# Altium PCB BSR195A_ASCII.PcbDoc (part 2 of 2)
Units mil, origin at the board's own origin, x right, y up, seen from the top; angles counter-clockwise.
Board outline 4000 x 3000 mil, 4 copper layers (Top Layer, Signal Layer 1, Signal Layer 2, Bottom Layer), stack 64.4 mil thick; 59 components, 14 nets, 91 pads, 35 vias.
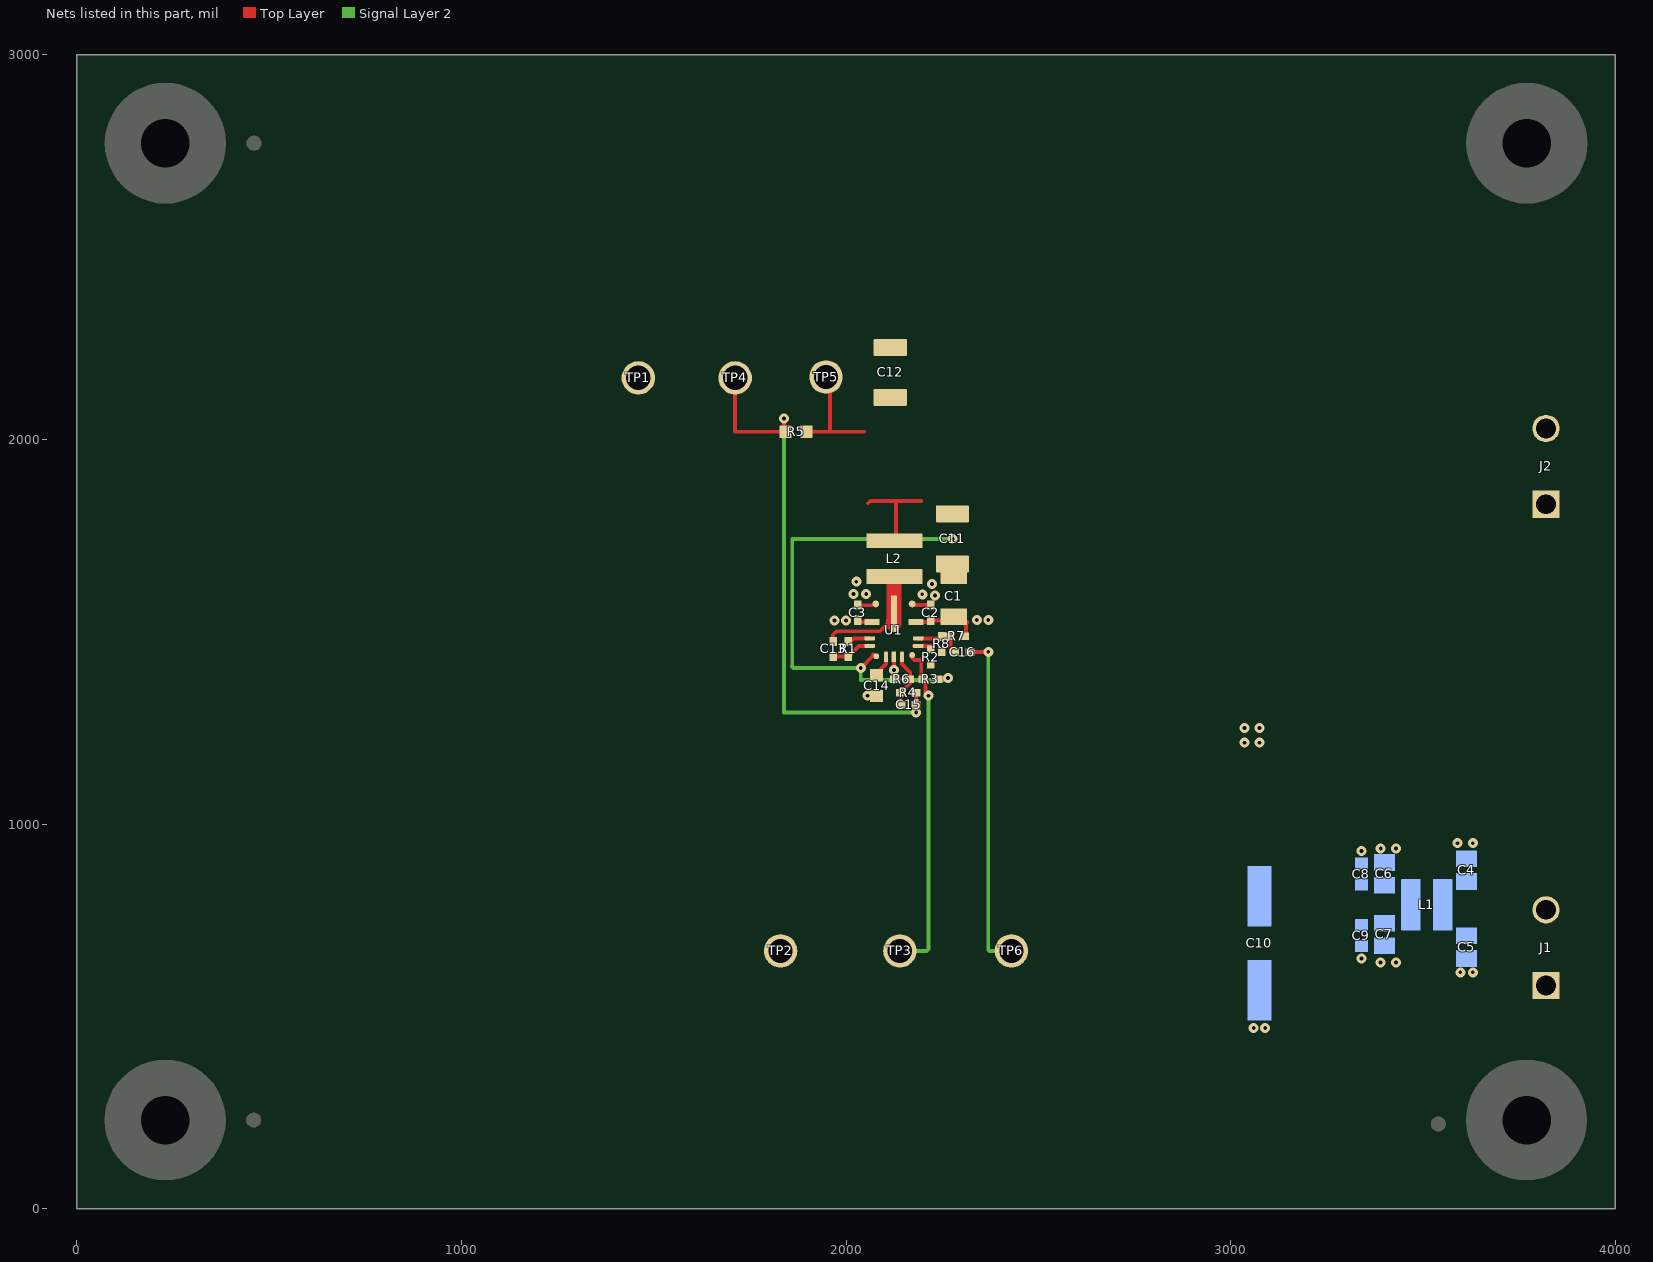
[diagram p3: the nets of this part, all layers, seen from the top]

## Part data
C1 C4 C5 C6 C7: library part CMP-0008814-2, "CAP, CERM, 2.2 uF, 50 V, +/- 10%, X7R, AEC-Q200 Grade 1, 1206"
C2 C3 C13: library part CMP-0006356-2, "CAP, CERM, 0.1 uF, 50 V, +/- 10%, X7R, AEC-Q200 Grade 1, 0402"
C8 C9: library part CMP-0008022-2, "CAP, CERM, 0.47 uF, 50 V, +/- 10%, X7R, AEC-Q200 Grade 1, 0805"
C10: library part CMP-0011168-2, "CAP, AL, 22 uF, 50 V, +/- 20%, 0.7 ohm, SMD"
C11 C12: library part CMP-0092443-1, "Multilayer Ceramic Capacitor 47uF 20% 10V 1210 T/R"
C14: library part CMP-0006831-4, "CAP, CERM, 1 uF, 16 V, +/- 10%, X7R, 0603"
C15: library part CMP-0006311-2, "CAP, CERM, 22 pF, 50 V, +/- 5%, C0G/NP0, AEC-Q200 Grade 1, 0402"
C16: library part CMP-0006314-2, "CAP, CERM, 1000 pF, 50 V, +/- 10%, X7R, AEC-Q200 Grade 1, 0402"
FID1 FID2 FID3 FID4 FID5 FID6: library part CMP-0077181-1, "Fiducial mark.  There is nothing to buy or mount."
H1 H2 H3 H4: library part CMP-0003617-1, "Machine Screw, Round, #4-40 x 1/4, Nylon, Philips panhead"
H5 H6 H7 H8: library part CMP-0003610-1
J1 J2: library part CMP-0054828-1, "Terminal Block, 5 mm, 2x1, Tin, TH"
L1: library part CMP-0087867-1, "1µH Shielded Molded Inductor 4A 32mOhm Max 2-SMD"
L2: library part CMP-0084012-1, "Inductor, Shielded, Metal Composite, 1.5 µH, 5.8 A, 0.019 ohm, SMD"
LBL1: library part CMP-0003625-1
Logo1: library part CMP-0074838-1, "Texas Instrument Corporate Signature"
Logo2: library part CMP-0074769-1
Logo3: library part CMP-0074847-1, "FCC_disclaimer"
LOGO4: library part CMP-0074837-1, "IEC 61010-1 Hot Surface Warning"
Logo5: library part CMP-0074844-1, "CE Mark"
R1: library part CMP-0081856-1, "RES, 0, 0%, 0.2 W, AEC-Q200 Grade 0, 0402"
R2: library part CMP-0091636-1, "5.9 kOhms ±1% 0.1W, 1/10W Chip Resistor 0402 (1005 Metric) Automotive AEC-Q200 Thick Film"
R3 R4 R8: library part CMP-0026768-2, "RES, 100 k, 0.5%, 0.063 W, AEC-Q200 Grade 0, 0402"
R5: library part CMP-0022736-4, "RES, 100, 1%, 0.1 W, 0603"
R6: library part CMP-0091635-1, "24.9 kOhms ±1% 0.1W, 1/10W Chip Resistor 0402 (1005 Metric) Automotive AEC-Q200 Thick Film"
R7: library part CMP-0026199-2, "RES, 255 k, 1%, 0.063 W, AEC-Q200 Grade 0, 0402"
TP1 TP2: library part CMP-0055148-1, "Test Point, Multipurpose, Black, TH"
TP3: library part CMP-0055149-1, "Test Point, Multipurpose, White, TH"
TP4 TP6: library part CMP-0055150-1, "Test Point, Multipurpose, Orange, TH"
TP5: library part CMP-0055147-1, "Test Point, Multipurpose, Red, TH"
U1: library part CMP-0092866-1, "3-V to 36-V, Low EMI Synchronous Step-Down Converter"
ZZ1: library part CMP-0077236-1
ZZ2: library part CMP-0077237-1
ZZ3: library part CMP-0077238-1
ZZ4: library part CMP-0077238-1, "These assemblies must comply with workmanship standards IPC-A-610 Class 2, unless otherwise specified."

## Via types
v1: diameter 26, hole 10, Top Layer to Bottom Layer, tented both sides, 35 vias

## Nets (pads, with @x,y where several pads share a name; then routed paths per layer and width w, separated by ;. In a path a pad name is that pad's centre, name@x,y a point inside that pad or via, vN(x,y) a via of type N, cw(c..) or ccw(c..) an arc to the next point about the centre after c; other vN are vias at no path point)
/RESET_PIN: R3.2 TP3.1 U1.5 | length 867.8
  Top Layer w10: U1.5@2169.9,1434.41 2177.77,1426.54 2195.49,1426.54 R3.2@2195.49,1380.79 ; R3.2@2199.75,1376.7 2206.4,1370.05 2206.4,1341.45 v1(2214.4,1333.45) v1@2214.4,1342.04
  Signal Layer 2 w10: TP3.1@2140,670 2210,670 2214.4,674.4 v1(2214.4,1333.45)
BIAS_PIN: C11.1 C12.1 J2.2 L2.2 R3.1 R5.1 TP5.1 U1.1 | length 1801
  Top Layer w10: R5.1@1904.43,2020 2047.52,2020 ; TP5.1@1931.81,2157.02 1958.83,2130 1958.83,2022.02 ; v1(2038.55,1405.54) 2070.47,1437.46 2070.47,1441.32 ; 2057.16,1834.04 2063.12,1840 2130,1840 ; L2.2@2130,1736.65 2130,1840 ; 2195.04,1840 2130,1840 ; R3.1@2240.52,1375.3 R3.1@2239.12,1376.7 2242.42,1380 v1(2264.92,1380)
  Signal Layer 2 w10: v1(2264.92,1380) 2259.05,1374.13 2038.86,1374.13 2038.55,1374.44 v1(2038.55,1405.54) 1863.16,1405.54 1858.99,1409.71 1860.11,1410.82 1860.11,1741.11 v1(2276.75,1741.11)
CBOOT_PIN: C13.1 R1.1 U1.14 | length 106.5
  Top Layer w10: C13.1@1966.55,1435.41 2006.61,1435.41 2034.15,1462.95 U1.14@2061.63,1462.95
EN_PIN: C16.1 R7.1 R8.2 U1.7 | length 119.4
  Top Layer w10: U1.7@2187.62,1482.64 R7.1@2269.97,1482.64 ; R7.1@2264.92,1487.69 R7.1@2269.97,1482.64 ; C16.1@2272.2,1453.65 2272.2,1480.4 R7.1@2269.97,1482.64
FB_PIN: C15.2 R4.1 R6.1 U1.4 | length 144.4
  Top Layer w10: C15.2@2143.13,1310 2142.34,1310.79 R4.1@2142.34,1341.3 2142.34,1341.79 2164.57,1364.02 2164.98,1364.02 R6.1@2164.98,1376.7 2167.24,1378.96 2167.24,1393.28 2150.5,1410.02 2150.5,1410.72 2145.29,1415.92 U1.4@2145.29,1434.41
GND: C1.2 C2.2 C3.2 C4.2 C5.2 C6.2 C7.2 C8.2 C9.2 C10.2 C11.2 C12.2 C14.2 J1.1 J2.1 R2.1 R6.2 R8.1 TP1.1 TP2.1 U1.3 U1.9 U1.11 | length 128.3
  Top Layer w10: C3.2@2030,1569.19 2030.5,1568.69 2067.21,1568.69 ; U1.3@2124.62,1434.41 2124.62,1383.47 R6.2@2124.94,1383.16 ; 2180.73,1569.25 2219.43,1569.25 C2.2@2220,1568.69
  other v1: 3060,470 3090,470 3597.2,614.53 3629.69,614.53 3390,640 3430,640 3340,650 3340,930 3390.32,936.1 3430,936.1 3590.31,950 3629.69,950 2055.49,1333.45 2124.62,1400 2231.46,1593.71 2198.35,1597.21 2019.58,1597.77 2052.62,1597.77 2223.8,1623.56 2026.7,1630
RBOOT_PIN: R1.2 U1.13 | length 61.3
  Top Layer w10: R1.2@2006.12,1468.74 2020.02,1482.64 U1.13@2061.63,1482.64
RT_PIN: R2.2 U1.6 | length 43.5
  Top Layer w10: U1.6@2176.47,1463.02 R2.2@2220,1463.02
SW_PIN: C13.2 L2.1 U1.10 | length 313.1
  Top Layer w10: C13.2@1965.55,1474.78 1965.55,1491.45 1975.4,1501.3 2088.68,1501.3 U1.10@2124.62,1537.24
  Top Layer w40: U1.10@2124.62,1521.02 2124.69,1546.61 2124.87,1623.56 2124.89,1633.35 2124.9,1638.91 L2.1@2124.91,1639.46
SYNC_clk: C16.2 TP6.1 | length 862.2
  Top Layer w10: C16.2@2333.62,1447.34 2356.77,1447.34 v1@2358.7,1449.27
  Signal Layer 2 w10: v1(2370,1447.75) 2370,672.36 2372.36,670 TP6.1@2430,670
VCC_PIN: C14.1 U1.2 | length 67
  Top Layer w10: C14.1@2079.35,1387.56 2079.35,1391.32 2103.96,1415.92 U1.2@2103.96,1434.41 ; C14.1@2087.22,1377.56 C14.1@2087.22,1387.56
VIN_EMI: C4.1 C5.1 J1.2 L1.1
VIN_PIN: C1.1 C2.1 C3.1 C6.1 C7.1 C8.1 C9.1 C10.1 L1.2 R7.2 U1.8 U1.12 | length 182.2
  Top Layer w10: C3.1@2030,1529.82 2034.85,1524.96 U1.12@2067.54,1524.96 ; U1.8@2181.71,1524.96 2215.65,1524.96 C2.1@2220,1529.32 2270.57,1529.32 C1.1@2280,1538.74 ; R7.2@2312.17,1487.69 2312.17,1521.69 2315.43,1524.96
  other v1: 3036.26,1211.28 3075.02,1211.28 3036.26,1250 3075.02,1250 1970,1529 2000,1529.32 2340,1530.42 2370,1530.42
VINJ: C15.1 R4.2 R5.2 TP4.1 | length 1457.4
  Top Layer w10: TP4.1@1711.84,2160 1711.84,2020 R5.2@1835.55,2020 ; R5.2@1838.5,2020 1838.55,2020.04 v1(1838.55,2054.04) ; R4.2@2181.71,1341.3 2181.71,1290.79 v1(2182.5,1290)
  Signal Layer 2 w10: v1(1838.55,2054.04) 1838.55,1290.04 v1(2182.5,1290) v1(2182.5,1290)
pads on no net: FID1.1 FID2.1 FID3.1 FID4.1 FID5.1 FID6.1 H1.1 H2.1 H3.1 H4.1 H5.0 H6.0 H7.0 H8.0 LBL1.0

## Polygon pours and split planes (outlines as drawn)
VINJ on Top Layer "fb-block-top" (solid, pour order 172): 2169.9,1318.86 2170,1318.76 2170,1281.03 2194.01,1281.03 2194.85,1280.19 2194.85,1318.83 2169.9,1318.83
GND on Top Layer "gnd-pin-top" (solid, pour order 170): 0,3000 3990,3000 3990,30 4000,20 0,20
BIAS_PIN on Top Layer "vout-top" (solid, pour order 160): 2040.21,1880 2040.21,1721.67 2034.65,1716.1 2335.12,1716.1 2335.12,1900 3886.39,1900 3886.39,2133.02 3873.83,2133.02 2038.75,2133.02 2038.75,1892.61
BIAS_PIN on Top Layer "bias-pin-top" (solid, pour order 152): 2030,1446.54 2030,1390.48 2048.43,1390.48 2048.88,1420 2086.92,1420 2087.07,1446.97 2031.05,1446.97
VCC_PIN on Top Layer "vcc-pin-top" (solid, pour order 158): 2087.07,1446.97 2086.92,1420.76 2073.41,1407.24 2063.12,1407.24 2063.12,1370 2106.08,1370 2106.08,1446.15 2087.22,1446.22
VIN_PIN on Top Layer "vin-pin-top" (solid, pour order 168): 1954.74,1510.5 2376.12,1510.5 2378.44,1508.19 2378.44,1560 1954.74,1560
/RESET_PIN on Top Layer "reset-pin-top" (solid, pour order 148): 2162.6,1447.61 2162.6,1365.32 2163.03,1364.89 2210,1364.89 2210,1445.93 2208.19,1447.75 2207.42,1446.97 2162.18,1446.97
GND on Signal Layer 2 "layer3_gnd" (solid, remove dead copper, pour order 166): 25.49,2974.51 25.49,25.49 3994.51,25.49 3974.51,45.49 3974.51,2974.51
VIN_PIN on Signal Layer 2 "vin-strap" (solid, pour order 145): 1955.45,1590 1955.45,1493.21 1954.95,1492.71 3010,1492.71 3010,1186.55 3011.28,1187.83 3100,1187.83 3100,1588.5 3098.5,1590
GND on Bottom Layer "BTM-GND-ALL" (solid, remove dead copper, pour order 162): 0,3950 4960,3950 4960,0 0,0
GND on Signal Layer 1 "TOP-GND-ALL" (solid, remove dead copper, pour order 164): 0,3000 0,0 3984.51,0 3984.51,3000

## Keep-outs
Keep-Out Layer:
  text ".Layer_Name" at 577,-858.49 h60

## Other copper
Top Layer:
  text ".Layer_Name" at 577,-858.49 h60
Bottom Layer:
  rectangle net VIN_EMI: 3570,730 3900,850.47
  rectangle net VIN_PIN: 2990,744.45 3110,1281.03
  rectangle net VIN_PIN: 2990,720 3490,860
  text ".Layer_Name" at 577,-858.49 h60

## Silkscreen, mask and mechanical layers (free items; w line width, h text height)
Top Overlay:
  rectangle: 30,440 1010,1310
  lines w10: 1940,1291.16 1940,1840 2345.31,1840 2345.31,1291.16 1941.16,1290
  text "VOUT" at 3430,2010 h60
  text "10mm x 14mm" at 1940,1870 h40
  text "BSR195A" at 70,1850 h40
  text "GND" at 3450,1800 h60
  text "VIN_EMI" at 3390,800 h60
  text "GND_EMI" at 3360,550 h60
  text ".Layer_Name" at 577,-858.49 h60
Bottom Overlay:
  text ".Layer_Name" at 577,-858.49 h60
Top Paste:
  text ".Layer_Name" at 577,-858.49 h60
Bottom Paste:
  text ".Layer_Name" at 577,-858.49 h60
Top Solder:
  text ".Layer_Name" at 577,-858.49 h60
  text ".Layer_Name" at 577,-858.49 h60
Bottom Solder:
  text ".Layer_Name" at 577,-858.49 h60
Drill Guide:
  text ".Layer_Name" at 577,-858.49 h60
M1 Board Outline:
  lines w10: 0,0 0,3000 4000,3000 4000,500 4000,0 0,0
  text ".Layer_Name" at 577,-858.49 h60
M2 Board Dimensions:
  rectangle: 0,-275 125,-150
  rectangle: 125,-400 500,-275
  lines w7: 0,-275 1000,-275 ; 0,-150 0,-400 1000,-400 1000,-150 ; 125,-400 125,-150 ; 250,-400 250,-150 ; 500,-400 500,-150 ; 700,-260 1700,-260 ; 750,-400 750,-150
  text ".Layer_Name" at 577,-858.49 h60
M3 3D STEP Top:
  text ".Layer_Name" at 577,-858.49 h60
M4 3D STEP Bottom:
  text ".Layer_Name" at 577,-858.49 h60
M5 Assembly Top:
  lines w10: -292,-930.17 6308,-930.17 ; -292,-726.83 6310,-726.83 ; -292,-523.5 -292,-1133.5 3713,-1133.5 6310,-1133.5 6310,-523.5 -291.5,-523.5 -291.5,-1133.5 1284,-1133.5 ; 2173,-1133.5 2173,-523.5 ; 3440,-726.83 3440,-523.5 ; 4280,-726.83 4280,-523.5 ; 4902,-1140 4902,-937.17
  text "COMPONENTS MARKED 'DNP' SHOULD NOT BE POPULATED." at 1153.5,-318.5 h60
  text "ASSEMBLY VARIANT:" at 1153,-434 h60
  text ".VariantName" at 2189,-434 h60
  text "PCB VIEWED FROM TOP SIDE" at -228.5,-655.67 h60
  text "BOARD #:" at 2248,-655.67 h60
  text ".PRJ_Number" at 2793.5,-655.67 h60
  text "REV:" at 3638,-655.67 h60
  text ".PCB_Rev" at 3929.5,-655.67 h60
  text "SVN REV:" at 4476,-655.67 h60
  text ".VersionControl_RevNumber" at 4982,-655.67 h60
  text "TID #:" at 2248,-859 h60
  text ".TID" at 2793.5,-859 h60
  text "PLOT NAME =" at -228.5,-1064.34 h60
  text ".plot_File_Name" at 577,-1064.34 h60
  text "GENERATED    :" at 2250,-1064.34 h60
  text ".Print_Date" at 3119.5,-1064.34 h60
  text ".Print_Time" at 3848.5,-1064.34 h60
  text "TEXAS INSTRUMENTS" at 5113,-1064.34 h60
M6 Assembly Bottom:
  lines w10: -292.5,-727.33 6309.5,-727.33 ; -290.5,-930.67 6309.5,-930.67 ; 1115.5,-1140.5 1115.5,-937.67 ; 1737.5,-727.33 1737.5,-524 ; 2577.5,-727.33 2577.5,-524 ; 3844.5,-1134 3844.5,-524 ; 4733.5,-1134 6309,-1134 6309,-524 -292.5,-524 -292.5,-1134 2304.5,-1134 6309.5,-1134 6309.5,-524
  text "COMPONENTS MARKED 'DNP' SHOULD NOT BE POPULATED." at 6102,-318 h60
  text ".VariantName" at 5058,-434 h60
  text "ASSEMBLY VARIANT:" at 6097,-434 h60
  text ".VersionControl_RevNumber" at 1035.5,-656.17 h60
  text "SVN REV:" at 1541.5,-656.17 h60
  text ".PCB_Rev" at 2088,-656.17 h60
  text "REV:" at 2379.5,-656.17 h60
  text ".PRJ_Number" at 3224,-656.17 h60
  text "BOARD #:" at 3769.5,-656.17 h60
  text "PCB VIEWED FROM BOTTOM SIDE" at 6246,-656.17 h60
  text ".TID" at 3224,-859.5 h60
  text "TID #:" at 3769.5,-859.5 h60
  text "TEXAS INSTRUMENTS" at 904.5,-1064.84 h60
  text ".Print_Time" at 2169,-1064.84 h60
  text ".Print_Date" at 2898,-1064.84 h60
  text "GENERATED    :" at 3767.5,-1064.84 h60
  text ".plot_File_Name" at 5440.5,-1064.84 h60
  text "PLOT NAME =" at 6246,-1064.84 h60
M9 Title Sheet:
  lines w10: -491.5,1041.5 -291.5,1041.5 ; -491.5,3416.5 -291.5,3416.5 ; -491.5,5791.5 -291.5,5791.5 ; 2008.5,-1333.5 2008.5,-1133.5 ; 2008.5,7966.5 2008.5,8166.5 ; 4508.5,-1333.5 4508.5,-1133.5 ; 4508.5,7966.5 4508.5,8166.5 ; 6321,-1133.5 6321,-523.5 11303.5,-523.5 ; 7008.5,-1333.5 7008.5,-1133.5 ; 7008.5,7966.5 7008.5,8166.5 ; 9508.5,-1333.5 9508.5,-1133.5 ; 9508.5,7966.5 9508.5,8166.5 ; 11303.5,-1133.5 11303.5,-523.5 ; 11303.5,-823.5 14303.5,-823.5 ; 11303.5,-223.5 14303.5,-223.5 ; 11304.5,370.5 14304.5,370.5 ; 12008.5,-1333.5 12008.5,-1133.5 ; 12008.5,7966.5 12008.5,8166.5 ; 12808.5,-1123.5 12808.5,-523.5 ; 14303.5,-523.5 11303.5,-523.5 ; 14303.5,76.5 11303.5,76.5 ; 14308.5,66.5 14308.5,-1133.5 ; 14308.5,871 11304.5,871 11303.5,871 11303.5,370.5 11303.5,76.5 ; 14308.5,1041.5 14508.5,1041.5 ; 14308.5,3416.5 14508.5,3416.5 ; 14308.5,5791.5 14508.5,5791.5 ; 11303.5,-523.5 11303.5,76.5 ; 14308.5,-1133.5 14308.5,7966.5 -291.5,7966.5 -291.5,-1133.5 14308.5,-1133.5 ; -491.5,-1333.5 -491.5,8166.5 14508.5,8166.5 14508.5,-1333.5 -491.5,-1333.5
  text "1" at 739.84,8036.5 h70
  text "2" at 3235.5,8036.5 h70
  text "3" at 5724.84,8036.5 h70
  text "4" at 8231.51,8036.5 h70
  text "5" at 10730.5,8036.5 h70
  text "6" at 13235.5,8036.5 h70
  text "A" at -416.5,6893.5 h70
  text "A" at 14383.5,6893.5 h70
  text "B" at -416.5,4513.5 h70
  text "B" at 14383.5,4513.5 h70
  text "C" at -416.5,2138.5 h70
  text "C" at 14383.5,2138.5 h70
  text "PROJECT TITLE:" at 11343.5,277.5 h45
  text ".PRJ_Title" at 11393.5,144.17 h70
  text "DESIGNED FOR:" at 11343.5,-23.5 h45
  text ".PRJ_Customer" at 11393.5,-163.5 h70
  text "D" at -416.5,-231.5 h70
  text "D" at 14383.5,-231.5 h70
  text "FILE NAME:" at 11343.5,-323.5 h45
  text ".PCB_File_Name_No_Path" at 11393.5,-443.5 h70
  text "Texas Instruments (TI) and/or its licensors do not warrant the accuracy or completeness of this specification" at 6374,-605.34 h45
  text "ENGINEER:" at 11343.5,-613.5 h45
  text "LAYOUT BY:" at 12848.5,-613.5 h45
  text "or any information contained therein. TI and/or its licensors do not warrant that this design will meet" at 6329.01,-718 h45
  text ".PRJ_Engineer" at 11393.5,-768.49 h70
  text ".PCB_Layout" at 12899,-768.49 h70
  text "the specifications, will be suitable for your application or fit for any particular purpose, or will operate in" at 6329.01,-830.67 h45
  text ".Layer_Name" at 577,-858.49 h60
  text "ALTIUM DESIGNER VERSION:" at 12848.5,-923.5 h45
  text "an implementation. TI and/or its licensors do not warrant that the design is production worthy. You should" at 6329.01,-943.33 h45
  text "completely validate and test your design implementation to confirm the system functionality for your application." at 6374,-1056 h45
  text ".print_Scale" at 11393.5,-1056.83 h70
  text ".Application_BuildNumber" at 12899,-1056.83 h70
  text "1" at 739.84,-1263.5 h70
  text "2" at 3235.5,-1263.5 h70
  text "3" at 5724.84,-1263.5 h70
  text "4" at 8231.51,-1263.5 h70
  text "5" at 10730.5,-1263.5 h70
  text "6" at 13235.5,-1263.5 h70
M10 Fab Notes:
  drawing of 189 lines, arcs and shapes, not listed
  text "DESIGN INFORMATION" at 12382.02,6356.17 h60
  text "MIN. TRACK WIDTH:" at 11737.46,6224.05 h60
  text "8" at 12833.7,6224.05 h60
  text "MIL" at 12988.46,6224.05 h60
  text "MIN. CLEARANCE:" at 11737.46,6099.92 h60
  text "0.2" at 12773.7,6099.93 h60
  text "mm" at 12988.46,6099.92 h60
  text "MIN. VIA PAD SIZE:" at 11737.46,5975.8 h60
  text "24" at 12803.71,5975.8 h60
  text "MIL" at 12988.46,5975.8 h60
  text "0.05mm (2MIL)" at 12432.46,5845.9 h60
  text "MINIMUM ANNULAR RING" at 11408.23,5837.67 h60
  text "EXTERNAL" at 13140.46,5837.67 h60
  text "PER" at 11608.23,5727.55 h60
  text "IPC-D-275 CLASS 2 LEVEL C" at 11828.23,5727.54 h60
  text "MIL, HOLES" at 13316.46,5627.07 h60
  text "+/-" at 12924,5618.48 h60
  text "+/-" at 13778,5618.48 h60
  text "REGISTRATION TOLERANCES:" at 11408.23,5617.42 h60
  text "METAL" at 12608,5617.42 h60
  text "5" at 13184.2,5617.42 h60
  text "3" at 14017.2,5617.42 h60
  text "MIL" at 14133.46,5617.42 h60
  text "HOLE SIZE TOLERANCE (UNLESS OTHERWISE SPECIFIED):" at 11408.23,5519.1 h60
  text "+/-" at 13778,5516.23 h60
  text "3" at 14017.2,5515.17 h60
  text "MIL" at 14133.46,5515.17 h60
  text "MATERIAL:" at 11333.46,5377.52 h60
  text "FR-4 High Tg" at 12319.9,5249 h60
  text "X" at 12175.46,5241.01 h60
  text "FR-408" at 11754.46,5236.49 h60
  text "OTHER" at 13242.46,5236.49 h60
  text "65 MIL (1.6mm) +/-10%" at 12074.56,5093.46 h60
  text "X" at 11954.46,5091.01 h60
  text "THICKNESS:" at 11408.23,5085.24 h60
  text "OTHER" at 13359.46,5085.24 h60
  text "TOLERANCE:" at 11408.23,4946.92 h60
  text "X" at 12256.46,4946.92 h60
  text "ANSI IPC-6012 TYPE 3 CLASS 2" at 12434.48,4946.92 h60
  text "OTHER +/-" at 12434.46,4802.73 h60
  text "BOW & TWIST:" at 11408.23,4657.54 h60
  text "X" at 12256.46,4657.54 h60
  text "ANSI IPC-6012 TYPE 3 CLASS 2" at 12434.48,4657.54 h60
  text "OTHER +/-" at 12434.46,4510.85 h60
  text "DRILLING:" at 11333.46,4380.23 h60
  text "NC_DRILL FILES" at 13094.46,4275.04 h60
  text "REFERENCE:" at 11408.23,4271.1 h60
  text "X" at 12065.46,4271.01 h60
  text "AS SHOWN" at 12243.46,4271.1 h60
  text "X" at 12966.46,4271.1 h60
  text "OTHER" at 13392.46,4128.85 h60
  text "PTH COPPER THICKNESS:" at 11407.91,4125.32 h60
  text "X" at 12547.14,4125.32 h60
  text "20-30 um" at 12675.14,4125.32 h60
  text "BOARD FINISH:" at 11333.46,3977.73 h60
  text "SILKSCREEN:" at 11488.68,3867.6 h60
  text "X" at 12446.46,3867.6 h60
  text "TOP" at 12563.46,3867.6 h60
  text "X" at 12956.46,3867.6 h60
  text "BOTTOM" at 13074.46,3867.6 h60
  text "SILKSCREEN COLOR:" at 11488.68,3712.41 h60
  text "X" at 12445.46,3712.41 h60
  text "WHITE" at 12563.46,3712.41 h60
  text "OTHER" at 13074.46,3712.41 h60
  text "X" at 12576.46,3568.96 h60
  text "GREEN" at 12694.46,3568.96 h60
  text "OTHER" at 13312.46,3568.96 h60
  text "SOLDER RESIST COLOR:" at 11488.68,3562.1 h60
  text "X" at 12576.46,3414.71 h60
  text "MATTE" at 12694.46,3414.71 h60
  text "SEMI-GLOSS" at 13312,3414.07 h60
  text "IMMERSION GOLD (ENIG)" at 12394.46,3241.94 h60
  text "ENEPIG" at 13732,3234.72 h60
  text "SURFACE FINISH:" at 11333.46,3233.72 h60
  text "X" at 12216.46,3233.72 h60
  text "IMM. TIN/SILVER OR EQUIV" at 11663,3096.4 h60
  text "OTHER" at 13094.46,3092.47 h60
  text "ARRAY/PANEL:" at 11333.46,2937.09 h60
  text "CUT AND TRIM PER M1 BOARD OUTLINE" at 12394.46,2928.87 h60
  text "N.C. ROUTE" at 12394.46,2792.9 h60
  text "X" at 13082.46,2792.9 h60
  text "V. SCORE" at 13260.46,2792.9 h60
  text "CERTIFICATION:" at 11333.46,2663.77 h60
  text "MATERIALS AND WORKMANSHIP FOR ALL PCBS" at 12058.46,2663.77 h60
  text "TO MEET OR EXCEED THE REQUIREMENTS OF:" at 12058.46,2569.71 h60
  text "X" at 11695.97,2441.08 h60
  text "ANSI IPC-A-600F CLASS ->" at 11823.96,2441.08 h60
  text "X" at 13471.97,2441.08 h60
  text "2" at 13581.96,2441.08 h60
  text "1" at 13266.96,2439.58 h60
  text "3" at 13935.96,2439.58 h60
  text "X" at 12507.97,2293.39 h60
  text "RoHS" at 12635.96,2293.39 h60
  text "OTHER" at 13280.36,2293.39 h60
  text "PER ORDER" at 13677.42,2293.39 h60
  text "ALL BOARDS MUST MEET OR EXCEED UL94-V0 REQUIREMENTS." at 11361,2139.57 h60
  text "PCB MUST BEAR THE UL94V-0 UL REGISTERED MATERIAL ID NUMBER" at 11361,2023.5 h60
  text "ADDITIONAL REQUIREMENTS:" at 11333.46,1854.08 h60
  text "MICROSECTION:" at 11408.23,1746.95 h60
  text "YES" at 12313.96,1746.95 h60
  text "REQUIRED" at 13175.46,1602.62 h60
  text "BARE BOARD ELEC. TEST:" at 11408.23,1599.76 h60
  text "NONE" at 12713.96,1599.76 h60
  text "X" at 13057.46,1599.76 h60
  text "PER ORDER" at 13767.46,1599.76 h60
  text "XX MIL VIAS REQUIRE NON-CONDUCTIVE FILL AND PLANARIZE" at 11576.38,1394.82 h59
  text "XX MIL VIAS REQUIRE CONDUCTIVE FILL AND PLANARIZE" at 11584.38,1290.84 h60
  text "OUTER XX MIL TRACES REQUIRE 50 OHM SINGLE-ENDED IMPEDANCE" at 11583.39,1127.46 h58
  text "LAYER 2 & 3 (INNER LAYERS) XX MIL WIDE, XX MIL SPACE / TRACES REQUIRE 100 OHM DIFFERENTIAL IMPEDANCE" at 11575.39,891.74 h60
  text "Note: Use the same finish as the rest of the board on the fingers on the edge of board. No solid gold needed." at 11430,330 h70
  text ".Layer_Name" at 577,-858.49 h60
M11 Gerber Information:
  lines w10: -292,-930.17 6308,-930.17 ; -292,-726.83 6310,-726.83 ; -292,-523.5 -292,-1133.5 3713,-1133.5 6310,-1133.5 6310,-523.5 -291.5,-523.5 -291.5,-1133.5 1284,-1133.5 ; 2173,-1133.5 2173,-523.5 ; 3440,-726.83 3440,-523.5 ; 4280,-726.83 4280,-523.5 ; 4902,-1140 4902,-937.17
  text "ALL ARTWORK VIEWED FROM TOP SIDE" at -228.5,-655.67 h60
  text "BOARD #:" at 2248,-655.67 h60
  text ".PRJ_Number" at 2793.5,-655.67 h60
  text "REV:" at 3638,-655.67 h60
  text ".PCB_Rev" at 3929.5,-655.67 h60
  text "SVN REV:" at 4476,-655.67 h60
  text ".VersionControl_RevNumber" at 4982,-655.67 h60
  text "LAYER NAME =" at -228.5,-858.49 h60
  text "TID #:" at 2248,-859 h60
  text ".TID" at 2793.5,-859 h60
  text "PLOT NAME =" at -228.5,-1064.34 h60
  text ".plot_File_Name" at 577,-1064.34 h60
  text "GENERATED    :" at 2250,-1064.34 h60
  text ".Print_Date" at 3119.5,-1064.34 h60
  text ".Print_Time" at 3848.5,-1064.34 h60
  text "TEXAS INSTRUMENTS" at 5113,-1064.34 h60
M12 Stackup:
  drawing of 295 lines, arcs and shapes, not listed
  text "Layer" at 9797.84,7760 h60
  text "Name" at 10207.76,7760 h60
  text "Material" at 11147.5,7760 h60
  text "Thickness" at 12007.26,7760 h60
  text "Constant" at 12657.1,7760 h60
  text "Board Layer Stack" at 13226.96,7760 h60
  text "1" at 9797.84,7640 h60
  text "Top Overlay" at 10207.76,7640 h60
  text "2" at 9797.84,7520 h60
  text "Top Solder" at 10207.76,7520 h60
  text "Solder Resist" at 11147.5,7520 h60
  text "0.40mil" at 12007.26,7520 h60
  text "3.5" at 12657.1,7520 h60
  text "3" at 9797.84,7400 h60
  text "Top Layer" at 10207.76,7400 h60
  text "Copper" at 11147.5,7400 h60
  text "2.80mil" at 12007.26,7400 h60
  text "4" at 9797.84,7280 h60
  text "Dielectric 1" at 10207.76,7280 h60
  text "FR-4 High Tg" at 11147.5,7280 h60
  text "8.00mil" at 12007.26,7280 h60
  text "4.2" at 12657.1,7280 h60
  text "5" at 9797.84,7160 h60
  text "Signal Layer 1" at 10207.76,7160 h60
  text "Copper" at 11147.5,7160 h60
  text "1.40mil" at 12007.26,7160 h60
  text "6" at 9797.84,7040 h60
  text "Dielectric 2" at 10207.76,7040 h60
  text "FR-4 High Tg" at 11147.5,7040 h60
  text "40.00mil" at 12007.26,7040 h60
  text "4.2" at 12657.1,7040 h60
  text "7" at 9797.84,6920 h60
  text "Signal Layer 2" at 10207.76,6920 h60
  text "Copper" at 11147.5,6920 h60
  text "1.40mil" at 12007.26,6920 h60
  text "8" at 9797.84,6800 h60
  text "Dielectric 3" at 10207.76,6800 h60
  text "FR-4 High Tg" at 11147.5,6800 h60
  text "8.00mil" at 12007.26,6800 h60
  text "4.2" at 12657.1,6800 h60
  text "9" at 9797.84,6680 h60
  text "Bottom Layer" at 10207.76,6680 h60
  text "Copper" at 11147.5,6680 h60
  text "2.80mil" at 12007.26,6680 h60
  text "10" at 9797.84,6560 h60
  text "Bottom Solder" at 10207.76,6560 h60
  text "Solder Resist" at 11147.5,6560 h60
  text "0.40mil" at 12007.26,6560 h60
  text "3.5" at 12657.1,6560 h60
  text "11" at 9797.84,6440 h60
  text "Bottom Overlay" at 10207.76,6440 h60
  text ".Layer_Name" at 577,-858.49 h60
M13 Component Bodies Top:
  text ".Layer_Name" at 577,-858.49 h60
M14 Component Bodies Bottom:
  text ".Layer_Name" at 577,-858.49 h60
M15 Courtyards Top:
  text ".Layer_Name" at 577,-858.49 h60
M16 Courtyards Bottom:
  text ".Layer_Name" at 577,-858.49 h60
Drill Drawing:
  circle w10: c5068.9,1607.91 r22.14
  lines w10: 5046.76,1696.47 5057.83,1696.47 5068.9,1685.4 5079.97,1696.47 5091.04,1696.47 5079.97,1707.54 5091.04,1718.6 5079.97,1718.6 5068.9,1729.67 5057.83,1718.6 5046.76,1718.6 5057.83,1707.54 5046.76,1696.47 ; 5046.76,1785.02 5091.04,1785.02 5091.04,1829.3 5046.76,1829.3 5046.76,1785.02 ; 5046.76,1906.78 5068.9,1884.64 5091.04,1906.78 5068.9,1928.92 5046.76,1906.78
  lines w12: 5006,1555.89 8118.94,1555.89 ; 5006,1954.38 8118.94,1954.38 ; 5321.63,1456.27 5321.63,2054 ; 5638.82,1456.27 5638.82,2054 ; 6260.56,1456.27 6260.56,2054 ; 6504.88,1456.27 6504.88,2054 ; 6865.22,1456.27 6865.22,2054 ; 7574.73,1456.27 7574.73,2054 ; 5006,1456.27 8118.94,1456.27 8118.94,2054 5006,2054 5006,1456.27
  text "Symbol" at 5065.77,1984.26 h72
  text "Quantity" at 5351.52,1984.26 h72
  text "Finished Hole Size" at 5668.7,1984.26 h72
  text "Plated" at 6290.45,1984.26 h72
  text "Hole Type" at 6534.77,1984.26 h72
  text "Drill Layer Pair" at 6895.11,1984.26 h72
  text "Hole Tolerance" at 7604.62,1984.26 h72
  text "35" at 5351.52,1884.64 h60
  text "10.00mil (0.254mm)" at 5668.7,1884.64 h60
  text "PTH" at 6290.45,1884.64 h60
  text "Round" at 6534.77,1884.64 h60
  text "Top Layer - Bottom Layer" at 6895.11,1884.64 h60
  text "4" at 5351.52,1785.02 h60
  text "51.18mil (1.300mm)" at 5668.7,1785.02 h60
  text "PTH" at 6290.45,1785.02 h60
  text "Round" at 6534.77,1785.02 h60
  text "Top Layer - Bottom Layer" at 6895.11,1785.02 h60
  text "6" at 5351.52,1685.4 h60
  text "63.00mil (1.600mm)" at 5668.7,1685.4 h60
  text "PTH" at 6290.45,1685.4 h60
  text "Round" at 6534.77,1685.4 h60
  text "Top Layer - Bottom Layer" at 6895.11,1685.4 h60
  text "4" at 5351.52,1585.77 h60
  text "125.98mil (3.200mm)" at 5668.7,1585.77 h60
  text "PTH" at 6290.45,1585.77 h60
  text "Round" at 6534.77,1585.77 h60
  text "Top Layer - Bottom Layer" at 6895.11,1585.77 h60
  text "49 Total" at 5351.52,1486.15 h60
  text ".Layer_Name" at 577,-858.49 h60
Mechanical 17:
  text ".Layer_Name" at 577,-858.49 h60
Mechanical 18:
  text ".Layer_Name" at 577,-858.49 h60
Mechanical 19:
  text ".Layer_Name" at 577,-858.49 h60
